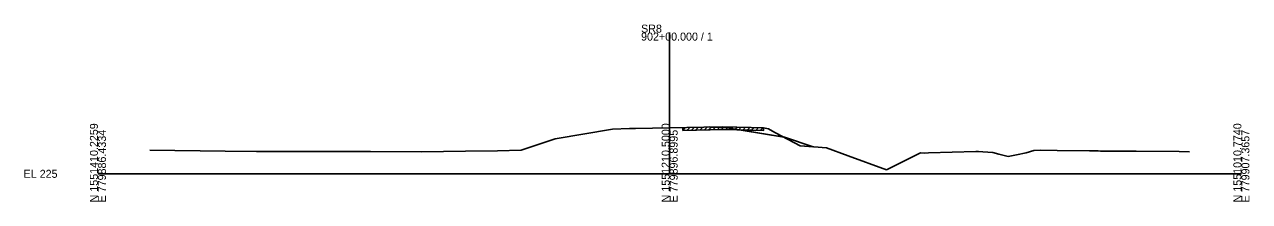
# Model space of a CAD drawing. Extents: x -26 to 787523, y -10 to 1545496.
# Drawn here: x -25.7 to 402.8, y 7490.3 to 7552.3 of the extents above; entities that cross this region are included whole.
import ezdxf

# ---------------------------------------------------------------- set-up
doc = ezdxf.new("R2010")
doc.units = 0
for name, color, linetype in [('50', 7, 'Continuous'), ('XS_CELL', 7, 'Continuous'), ('XS_M_SHAPES_EARTHWORK', 7, 'Continuous'), ('XS_P_FINISHED_GRADE', 7, 'Continuous'), ('XS_X_GROUND', 7, 'Continuous')]:
    doc.layers.add(name, color=color, linetype=linetype)

msp = doc.modelspace()

# ---------------------------------------------------------------- linework, layer by layer
at = {"layer": '50'}
for p, q in [((218.08, 7515.47), (219.08, 7516.46)), ((204.56, 7515.16), (205.58, 7516.18)), ((204.56, 7515.16), (204.56, 7516.16)), ((204.56, 7515.16), (214.15, 7515.38)), ((206.06, 7515.19), (207.08, 7516.21)), ((207.56, 7515.22), (208.59, 7516.25)), ((209.06, 7515.26), (210.09, 7516.28)), ((210.57, 7515.29), (211.59, 7516.32)), ((212.07, 7515.33), (213.1, 7516.35)), ((213.57, 7515.36), (214.6, 7516.39)), ((214.15, 7515.38), (218.54, 7515.48)), ((215.08, 7515.4), (216.1, 7516.42)), ((216.58, 7515.43), (217.6, 7516.46)), ((218.54, 7515.48), (228.49, 7515.24)), ((219.58, 7515.45), (220.56, 7516.43)), ((221.09, 7515.42), (222.07, 7516.39)), ((222.59, 7515.38), (223.57, 7516.36)), ((224.09, 7515.34), (225.07, 7516.32)), ((225.6, 7515.31), (226.57, 7516.28)), ((227.1, 7515.27), (228.08, 7516.25)), ((228.49, 7515.24), (232.78, 7515.14)), ((228.6, 7515.24), (229.58, 7516.21)), ((230.11, 7515.2), (231.08, 7516.18)), ((231.61, 7515.16), (232.59, 7516.14)), ((232.78, 7516.14), (232.78, 7515.14))]:
    msp.add_line(p, q, dxfattribs=at)
at = {"layer": 'XS_CELL'}
for p, q in [((200, 7500), (200, 7549.43)), ((0, 7500), (200, 7500)), ((200, 7500), (400, 7500))]:
    msp.add_line(p, q, dxfattribs=at)
at = {"layer": 'XS_M_SHAPES_EARTHWORK'}
for points in [[(228.49, 7516.24), (232.78, 7516.14), (232.78, 7515.14), (228.49, 7515.24), (225.03, 7515.32), (220.15, 7516.14), (214.74, 7516.39), (218.54, 7516.48)], [(228.49, 7516.24), (232.78, 7516.14), (232.78, 7515.14), (228.49, 7515.24), (225.03, 7515.32), (220.15, 7516.14), (214.74, 7516.39), (218.54, 7516.48)], [(214.15, 7516.38), (214.74, 7516.39), (214, 7516.42), (214, 7516.37)], [(214.15, 7516.38), (214.74, 7516.39), (214, 7516.42), (214, 7516.37)], [(232.78, 7516.14), (232.78, 7515.14), (228.49, 7515.24), (225.03, 7515.32), (239.91, 7512.84), (236.76, 7514.52), (234.52, 7515.72)], [(232.78, 7516.14), (232.78, 7515.14), (228.49, 7515.24), (225.03, 7515.32), (239.91, 7512.84), (236.76, 7514.52), (234.52, 7515.72)], [(239.91, 7512.84), (240.12, 7512.81), (250.18, 7509.45), (245.62, 7509.79)], [(239.91, 7512.84), (240.12, 7512.81), (250.18, 7509.45), (245.62, 7509.79)]]:
    msp.add_lwpolyline(points, close=True, dxfattribs=at)
at = {"layer": 'XS_P_FINISHED_GRADE'}
for p, q in [((214, 7516.42), (220.15, 7516.14)), ((220.15, 7516.14), (240.12, 7512.81)), ((240.12, 7512.81), (250.18, 7509.45))]:
    msp.add_line(p, q, dxfattribs=at)
at = {"layer": 'XS_X_GROUND'}
for p, q in [((214.15, 7516.38), (218.54, 7516.48)), ((218.54, 7516.48), (228.49, 7516.24)), ((148.1, 7508.32), (160, 7512.29)), ((160, 7512.29), (180, 7515.62)), ((180, 7515.62), (186, 7515.86)), ((186, 7515.86), (188, 7515.9)), ((188, 7515.9), (200, 7516.14)), ((200, 7516.14), (212, 7516.38)), ((212, 7516.38), (214, 7516.42)), ((214, 7516.42), (214, 7516.37)), ((214, 7516.37), (214.15, 7516.38)), ((228.49, 7516.24), (232.78, 7516.14)), ((232.78, 7516.14), (234.52, 7515.72)), ((234.52, 7515.72), (236.76, 7514.52)), ((236.76, 7514.52), (245.62, 7509.79)), ((18.13, 7508.27), (44.51, 7507.97)), ((44.51, 7507.97), (55.49, 7507.85)), ((113.23, 7507.73), (128.55, 7507.92)), ((128.55, 7507.92), (139.79, 7508.07)), ((139.79, 7508.07), (148.1, 7508.32)), ((245.62, 7509.79), (250.4, 7509.44)), ((250.4, 7509.44), (254.85, 7509.1)), ((254.85, 7509.1), (262.46, 7506.29)), ((324.71, 7507.36), (327.45, 7508.17)), ((327.45, 7508.17), (329.6, 7508.26)), ((329.6, 7508.26), (335.6, 7508.19)), ((335.6, 7508.19), (346.89, 7508.03)), ((346.89, 7508.03), (349.5, 7507.99)), ((349.5, 7507.99), (349.91, 7507.99)), ((349.91, 7507.99), (350.75, 7507.98)), ((350.75, 7507.98), (363.25, 7507.9)), ((363.25, 7507.9), (378.27, 7507.78)), ((55.49, 7507.85), (95.32, 7507.78)), ((95.32, 7507.78), (113.23, 7507.73)), ((262.46, 7506.29), (275.89, 7501.39)), ((279.59, 7503.23), (287.72, 7507.3)), ((287.72, 7507.3), (289.31, 7507.24)), ((289.31, 7507.24), (290.56, 7507.3)), ((290.56, 7507.3), (307.07, 7507.76)), ((307.07, 7507.76), (308.08, 7507.82)), ((308.08, 7507.82), (309.53, 7507.73)), ((309.53, 7507.73), (313, 7507.5)), ((313, 7507.5), (315.17, 7506.93)), ((315.17, 7506.93), (318.36, 7506.1)), ((318.36, 7506.1), (321.28, 7506.59)), ((321.28, 7506.59), (324.71, 7507.36)), ((378.27, 7507.78), (381.9, 7507.72)), ((275.89, 7501.39), (279.59, 7503.23))]:
    msp.add_line(p, q, dxfattribs=at)

# ---------------------------------------------------------------- texts
at = {"layer": 'XS_CELL'}
for s, p in [('SR8', (190, 7549.43)), ('902+00.000 / 1', (190, 7546.63)), ('EL 225', (-26, 7498.6))]:
    msp.add_text(s, height=2.8, dxfattribs=at).set_placement(p)
for s, p in [('N 1551410.2259', (0, 7490)), ('N 1551210.5000', (200, 7490)), ('N 1551010.7740', (400, 7490)), ('E 779886.4334', (2.8, 7490)), ('E 779896.8995', (202.8, 7490)), ('E 779907.3657', (402.8, 7490))]:
    msp.add_text(s, height=2.8, rotation=90, dxfattribs=at).set_placement(p)

doc.saveas('drawing.dxf')
